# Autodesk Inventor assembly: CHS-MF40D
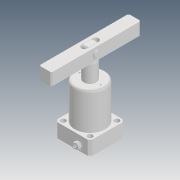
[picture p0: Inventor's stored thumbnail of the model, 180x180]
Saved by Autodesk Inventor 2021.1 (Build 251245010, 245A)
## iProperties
Created: 2019-04
Part Number: CHS-MF40D
Description: STEP AP203
Document SubType Name: Assembly
Designer: user
Title: chs-mf40d_asm.STEP
Revision Number: ÈÎºÎ
Sending System: SolidWorks 2017
Preprocessor: SwSTEP 2.0
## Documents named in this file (10)
- D:\Vault_2016\Projekty\Clamptek\Hydraulic\CHS\CHS-40\Inventor\CHS-MF40D\CHS-MF40D.iam
- D:\Vault_2016\Projekty\Clamptek\Hydraulic\CHS\CHS-40\Inventor\CHS-MF40D\CHS-MF40-03.ipt
- D:\Vault_2016\Projekty\Clamptek\Hydraulic\CHS\CHS-40\Inventor\CHS-MF40D\CHS-TXF-01.ipt
- D:\Vault_2016\Projekty\Clamptek\Hydraulic\CHS\CHS-40\Inventor\CHS-MF40D\CHS-MF40-TXF-03.ipt
- D:\Vault_2016\Projekty\Clamptek\Hydraulic\CHS\CHS-40\Inventor\CHS-MF40D\CHS-MF40-TXF-02.ipt
- D:\Vault_2016\Projekty\Clamptek\Hydraulic\CHS\CHS-40\Inventor\CHS-MF40D\M6.ipt
- D:\Vault_2016\Projekty\Clamptek\Hydraulic\CHS\CHS-40\Inventor\CHS-MF40D\CHS-40D-02_4.ipt
- D:\Vault_2016\Projekty\Clamptek\Hydraulic\CHS\CHS-40\Inventor\CHS-MF40D\CHS-40D-01_5.ipt
- D:\Vault_2016\Projekty\Clamptek\Hydraulic\CHS\CHS-40\Inventor\CHS-MF40D\XIAO.ipt
- D:\Vault_2016\Projekty\Clamptek\Hydraulic\CHS\CHS-40\Inventor\CHS-MF40D\12ÖáÓÃµ²È¦.ipt
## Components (10 placed, 10 different names)
1. CHS-MF40-03_1
2. CHS-TXF-01_2
3. CHS-MF40-TXF-03_3
4. CHS-MF40-TXF-02_4
5. M6_5
6. CHS-40D-02_4_6
7. CHS-40D-01_5_7
8. XIAO_8
9. 12ÖáÓÃµ²È¦_9
10. 12ÖáÓÃµ²È¦_10
